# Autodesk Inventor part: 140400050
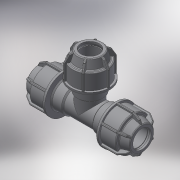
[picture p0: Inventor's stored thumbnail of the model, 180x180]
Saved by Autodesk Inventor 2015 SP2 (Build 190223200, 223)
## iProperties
Created: 2017-08
Part Number: 140400050
Material: Generic
Description: PLASSON L.14 TEE (SILVER) 50-50-50
Document SubType Name: Modeling
Designer: KIM
Density: 1 g/cm^3
Appearance: Default
Author: KIM
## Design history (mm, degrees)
derived "140400.ipt"
feature "Solid1::140400.ipt"
tag "TaggingFeature1"
body "Solid1"
other parameters: "d2" = 74, "d4" = 15 deg, "d5" = 48.84, "d6" = 16.1172, "d10" = 92, "d16" = 51, "d17" = 3.7, "d24" = 3.7, "d25" = 82.8, "d26" = 69, "d27" = 3.7, "d28" = 135 deg, "d29" = 2.22, "d31" = 2.5, "d46" = 150 deg, "d49" = 4.6, "d50" = 0, "d58" = 1.5, "d61" = 360 deg, "d63" = 45, "d64" = 103.5, "d78" = 180 deg, "d80" = 63, "d81" = 3.5, "d84" = 7.4, "d86" = 0, "d88" = 0, "d90" = 0, "d92" = 180 deg, "G_" = 18.631, "E_" = 92, "H_" = 207, "l_" = 74, "l_2" = 19
